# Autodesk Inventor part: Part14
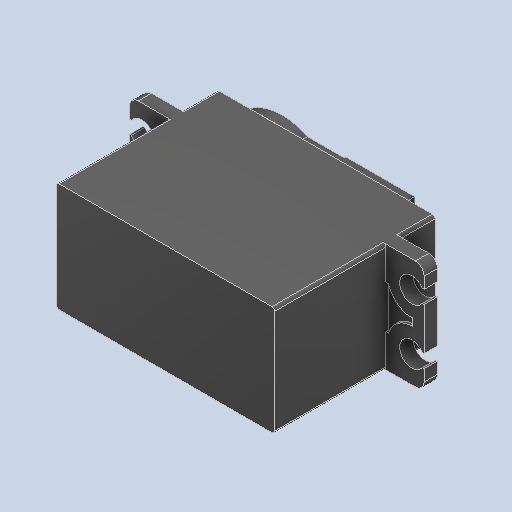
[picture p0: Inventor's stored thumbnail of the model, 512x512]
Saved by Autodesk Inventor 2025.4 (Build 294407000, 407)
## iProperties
Created: 2026-09
Part Number: Part14
Material: Generic
Document SubType Name: Modeling
Designer: AdminForWorker
Density: 1 g/cm^3
Appearance: Default
Author: AdminForWorker
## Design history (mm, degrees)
feature "Body1"
body "Solid1"
